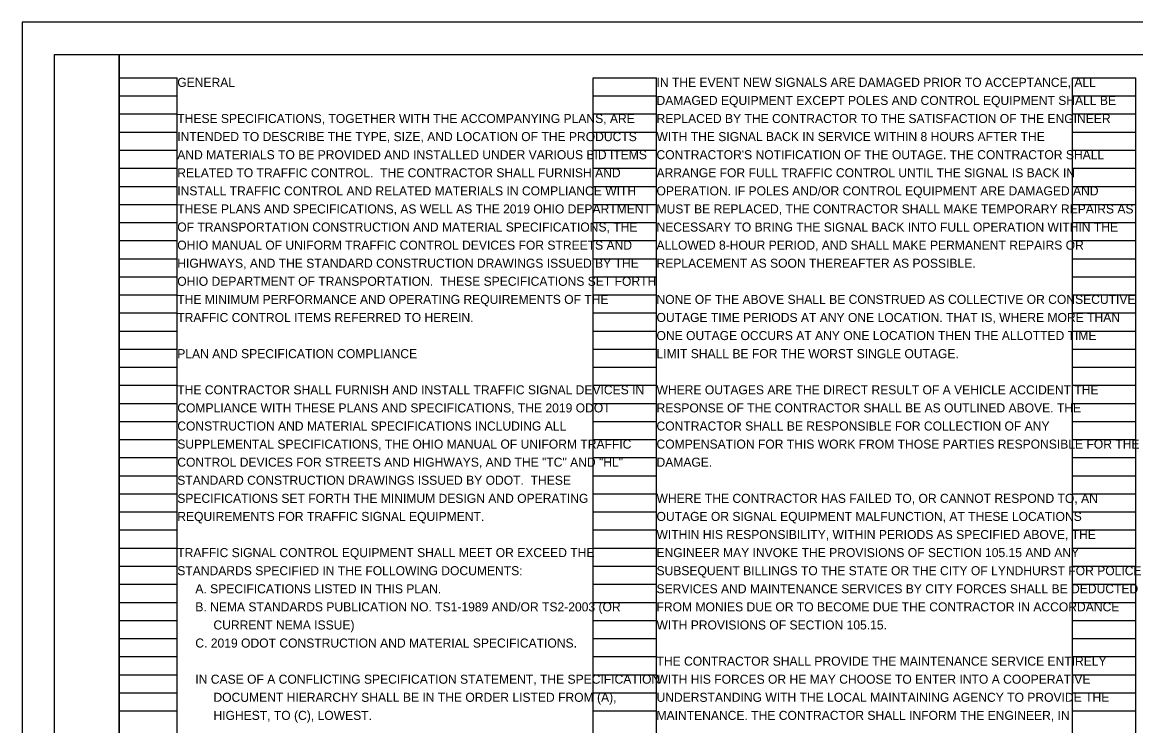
# Model space of a CAD drawing. Extents: x 0 to 34, y -30 to 22.
# Drawn here: x 0 to 17.24, y 11.11 to 22 of the extents above; entities that cross this region are included whole.
import ezdxf

# ---------------------------------------------------------------- set-up
doc = ezdxf.new("R2010")
doc.units = 0
for name, color, linetype in [('SH_Border', 7, 'Continuous'), ('SH_Cut_Line', 7, 'Continuous'), ('SH_Data', 7, 'Continuous'), ('SH_Text', 7, 'Continuous')]:
    doc.layers.add(name, color=color, linetype=linetype)

msp = doc.modelspace()

# ---------------------------------------------------------------- linework, layer by layer
at = {"layer": 'SH_Border'}
for points in [[(0.5, 21.5), (1.5, 21.5), (1.5, 0.5), (0.5, 0.5)], [(1.5, 21.5), (33.5, 21.5), (33.5, 0.5), (1.5, 0.5)]]:
    msp.add_lwpolyline(points, close=True, dxfattribs=at)
at = {"layer": 'SH_Cut_Line'}
msp.add_lwpolyline([(0, 0), (34, 0), (34, 22), (0, 22)], close=True, dxfattribs=at)
at = {"layer": 'SH_Data'}
for p, q in [((1.5, 0.98), (1.5, 21.14)), ((1.5, 21.14), (2.4, 21.14)), ((2.4, 0.98), (2.4, 21.14)), ((8.84, 0.98), (8.84, 21.14)), ((8.84, 21.14), (9.82, 21.14)), ((9.82, 0.98), (9.82, 21.14)), ((16.26, 0.98), (16.26, 21.14)), ((16.26, 21.14), (17.24, 21.14)), ((17.24, 0.98), (17.24, 21.14)), ((1.5, 20.86), (2.4, 20.86)), ((8.84, 20.86), (9.82, 20.86)), ((16.26, 20.86), (17.24, 20.86)), ((1.5, 20.58), (2.4, 20.58)), ((8.84, 20.58), (9.82, 20.58)), ((16.26, 20.58), (17.24, 20.58)), ((1.5, 20.3), (2.4, 20.3)), ((8.84, 20.3), (9.82, 20.3)), ((16.26, 20.3), (17.24, 20.3)), ((1.5, 20.02), (2.4, 20.02)), ((8.84, 20.02), (9.82, 20.02)), ((16.26, 20.02), (17.24, 20.02)), ((1.5, 19.74), (2.4, 19.74)), ((8.84, 19.74), (9.82, 19.74)), ((16.26, 19.74), (17.24, 19.74)), ((1.5, 19.46), (2.4, 19.46)), ((8.84, 19.46), (9.82, 19.46)), ((16.26, 19.46), (17.24, 19.46)), ((1.5, 19.18), (2.4, 19.18)), ((8.84, 19.18), (9.82, 19.18)), ((16.26, 19.18), (17.24, 19.18)), ((1.5, 18.9), (2.4, 18.9)), ((8.84, 18.9), (9.82, 18.9)), ((16.26, 18.9), (17.24, 18.9)), ((1.5, 18.62), (2.4, 18.62)), ((8.84, 18.62), (9.82, 18.62)), ((16.26, 18.62), (17.24, 18.62)), ((1.5, 18.34), (2.4, 18.34)), ((8.84, 18.34), (9.82, 18.34)), ((16.26, 18.34), (17.24, 18.34)), ((1.5, 18.06), (2.4, 18.06)), ((8.84, 18.06), (9.82, 18.06)), ((16.26, 18.06), (17.24, 18.06)), ((1.5, 17.78), (2.4, 17.78)), ((8.84, 17.78), (9.82, 17.78)), ((16.26, 17.78), (17.24, 17.78)), ((1.5, 17.5), (2.4, 17.5)), ((8.84, 17.5), (9.82, 17.5)), ((16.26, 17.5), (17.24, 17.5)), ((1.5, 17.22), (2.4, 17.22)), ((8.84, 17.22), (9.82, 17.22)), ((16.26, 17.22), (17.24, 17.22)), ((1.5, 16.94), (2.4, 16.94)), ((8.84, 16.94), (9.82, 16.94)), ((16.26, 16.94), (17.24, 16.94)), ((1.5, 16.66), (2.4, 16.66)), ((8.84, 16.66), (9.82, 16.66)), ((16.26, 16.66), (17.24, 16.66)), ((1.5, 16.38), (2.4, 16.38)), ((8.84, 16.38), (9.82, 16.38)), ((16.26, 16.38), (17.24, 16.38)), ((1.5, 16.1), (2.4, 16.1)), ((8.84, 16.1), (9.82, 16.1)), ((16.26, 16.1), (17.24, 16.1)), ((1.5, 15.82), (2.4, 15.82)), ((8.84, 15.82), (9.82, 15.82)), ((16.26, 15.82), (17.24, 15.82)), ((1.5, 15.54), (2.4, 15.54)), ((8.84, 15.54), (9.82, 15.54)), ((16.26, 15.54), (17.24, 15.54)), ((1.5, 15.26), (2.4, 15.26)), ((8.84, 15.26), (9.82, 15.26)), ((16.26, 15.26), (17.24, 15.26)), ((1.5, 14.98), (2.4, 14.98)), ((8.84, 14.98), (9.82, 14.98)), ((16.26, 14.98), (17.24, 14.98)), ((1.5, 14.7), (2.4, 14.7)), ((8.84, 14.7), (9.82, 14.7)), ((16.26, 14.7), (17.24, 14.7)), ((1.5, 14.42), (2.4, 14.42)), ((8.84, 14.42), (9.82, 14.42)), ((16.26, 14.42), (17.24, 14.42)), ((1.5, 14.14), (2.4, 14.14)), ((8.84, 14.14), (9.82, 14.14)), ((16.26, 14.14), (17.24, 14.14)), ((1.5, 13.86), (2.4, 13.86)), ((8.84, 13.86), (9.82, 13.86)), ((16.26, 13.86), (17.24, 13.86)), ((1.5, 13.58), (2.4, 13.58)), ((8.84, 13.58), (9.82, 13.58)), ((16.26, 13.58), (17.24, 13.58)), ((1.5, 13.3), (2.4, 13.3)), ((8.84, 13.3), (9.82, 13.3)), ((16.26, 13.3), (17.24, 13.3)), ((1.5, 13.02), (2.4, 13.02)), ((8.84, 13.02), (9.82, 13.02)), ((16.26, 13.02), (17.24, 13.02)), ((1.5, 12.74), (2.4, 12.74)), ((8.84, 12.74), (9.82, 12.74)), ((16.26, 12.74), (17.24, 12.74)), ((1.5, 12.46), (2.4, 12.46)), ((8.84, 12.46), (9.82, 12.46)), ((16.26, 12.46), (17.24, 12.46)), ((1.5, 12.18), (2.4, 12.18)), ((8.84, 12.18), (9.82, 12.18)), ((16.26, 12.18), (17.24, 12.18)), ((1.5, 11.9), (2.4, 11.9)), ((8.84, 11.9), (9.82, 11.9)), ((16.26, 11.9), (17.24, 11.9)), ((1.5, 11.62), (2.4, 11.62)), ((8.84, 11.62), (9.82, 11.62)), ((16.26, 11.62), (17.24, 11.62)), ((1.5, 11.34), (2.4, 11.34)), ((8.84, 11.34), (9.82, 11.34)), ((16.26, 11.34), (17.24, 11.34))]:
    msp.add_line(p, q, dxfattribs=at)

# ---------------------------------------------------------------- texts
at = {"layer": 'SH_Text'}
for s, p in [('GENERAL', (2.4, 21)), ('IN THE EVENT NEW SIGNALS ARE DAMAGED PRIOR TO ACCEPTANCE, ALL ', (9.82, 21)), ('DAMAGED EQUIPMENT EXCEPT POLES AND CONTROL EQUIPMENT SHALL BE ', (9.82, 20.72)), ('THESE SPECIFICATIONS, TOGETHER WITH THE ACCOMPANYING PLANS, ARE ', (2.4, 20.44)), ('REPLACED BY THE CONTRACTOR TO THE SATISFACTION OF THE ENGINEER ', (9.82, 20.44)), ('INTENDED TO DESCRIBE THE TYPE, SIZE, AND LOCATION OF THE PRODUCTS ', (2.4, 20.16)), ('WITH THE SIGNAL BACK IN SERVICE WITHIN 8 HOURS AFTER THE ', (9.82, 20.16)), ('AND MATERIALS TO BE PROVIDED AND INSTALLED UNDER VARIOUS BID ITEMS ', (2.4, 19.88)), ("CONTRACTOR'S NOTIFICATION OF THE OUTAGE. THE CONTRACTOR SHALL ", (9.82, 19.88)), ('RELATED TO TRAFFIC CONTROL.  THE CONTRACTOR SHALL FURNISH AND ', (2.4, 19.6)), ('ARRANGE FOR FULL TRAFFIC CONTROL UNTIL THE SIGNAL IS BACK IN ', (9.82, 19.6)), ('INSTALL TRAFFIC CONTROL AND RELATED MATERIALS IN COMPLIANCE WITH ', (2.4, 19.32)), ('OPERATION. IF POLES AND/OR CONTROL EQUIPMENT ARE DAMAGED AND ', (9.82, 19.32)), ('THESE PLANS AND SPECIFICATIONS, AS WELL AS THE 2019 OHIO DEPARTMENT ', (2.4, 19.04)), ('MUST BE REPLACED, THE CONTRACTOR SHALL MAKE TEMPORARY REPAIRS AS ', (9.82, 19.04)), ('OF TRANSPORTATION CONSTRUCTION AND MATERIAL SPECIFICATIONS, THE ', (2.4, 18.76)), ('NECESSARY TO BRING THE SIGNAL BACK INTO FULL OPERATION WITHIN THE ', (9.82, 18.76)), ('OHIO MANUAL OF UNIFORM TRAFFIC CONTROL DEVICES FOR STREETS AND ', (2.4, 18.48)), ('ALLOWED 8-HOUR PERIOD, AND SHALL MAKE PERMANENT REPAIRS OR ', (9.82, 18.48)), ('HIGHWAYS, AND THE STANDARD CONSTRUCTION DRAWINGS ISSUED BY THE ', (2.4, 18.2)), ('REPLACEMENT AS SOON THEREAFTER AS POSSIBLE.', (9.82, 18.2)), ('OHIO DEPARTMENT OF TRANSPORTATION.  THESE SPECIFICATIONS SET FORTH ', (2.4, 17.92)), ('THE MINIMUM PERFORMANCE AND OPERATING REQUIREMENTS OF THE ', (2.4, 17.64)), ('NONE OF THE ABOVE SHALL BE CONSTRUED AS COLLECTIVE OR CONSECUTIVE ', (9.82, 17.64)), ('TRAFFIC CONTROL ITEMS REFERRED TO HEREIN.', (2.4, 17.36)), ('OUTAGE TIME PERIODS AT ANY ONE LOCATION. THAT IS, WHERE MORE THAN ', (9.82, 17.36)), ('ONE OUTAGE OCCURS AT ANY ONE LOCATION THEN THE ALLOTTED TIME ', (9.82, 17.08)), ('PLAN AND SPECIFICATION COMPLIANCE', (2.4, 16.8)), ('LIMIT SHALL BE FOR THE WORST SINGLE OUTAGE.', (9.82, 16.8)), ('THE CONTRACTOR SHALL FURNISH AND INSTALL TRAFFIC SIGNAL DEVICES IN ', (2.4, 16.24)), ('WHERE OUTAGES ARE THE DIRECT RESULT OF A VEHICLE ACCIDENT THE ', (9.82, 16.24)), ('COMPLIANCE WITH THESE PLANS AND SPECIFICATIONS, THE 2019 ODOT ', (2.4, 15.96)), ('RESPONSE OF THE CONTRACTOR SHALL BE AS OUTLINED ABOVE. THE ', (9.82, 15.96)), ('CONSTRUCTION AND MATERIAL SPECIFICATIONS INCLUDING ALL ', (2.4, 15.68)), ('CONTRACTOR SHALL BE RESPONSIBLE FOR COLLECTION OF ANY ', (9.82, 15.68)), ('SUPPLEMENTAL SPECIFICATIONS, THE OHIO MANUAL OF UNIFORM TRAFFIC ', (2.4, 15.4)), ('COMPENSATION FOR THIS WORK FROM THOSE PARTIES RESPONSIBLE FOR THE ', (9.82, 15.4)), ('CONTROL DEVICES FOR STREETS AND HIGHWAYS, AND THE "TC" AND "HL" ', (2.4, 15.12)), ('DAMAGE.', (9.82, 15.12)), ('STANDARD CONSTRUCTION DRAWINGS ISSUED BY ODOT.  THESE ', (2.4, 14.84)), ('SPECIFICATIONS SET FORTH THE MINIMUM DESIGN AND OPERATING ', (2.4, 14.56)), ('WHERE THE CONTRACTOR HAS FAILED TO, OR CANNOT RESPOND TO, AN ', (9.82, 14.56)), ('REQUIREMENTS FOR TRAFFIC SIGNAL EQUIPMENT.  ', (2.4, 14.28)), ('OUTAGE OR SIGNAL EQUIPMENT MALFUNCTION, AT THESE LOCATIONS ', (9.82, 14.28)), ('WITHIN HIS RESPONSIBILITY, WITHIN PERIODS AS SPECIFIED ABOVE, THE ', (9.82, 14)), ('TRAFFIC SIGNAL CONTROL EQUIPMENT SHALL MEET OR EXCEED THE ', (2.4, 13.72)), ('ENGINEER MAY INVOKE THE PROVISIONS OF SECTION 105.15 AND ANY ', (9.82, 13.72)), ('STANDARDS SPECIFIED IN THE FOLLOWING DOCUMENTS:', (2.4, 13.44)), ('SUBSEQUENT BILLINGS TO THE STATE OR THE CITY OF LYNDHURST FOR POLICE ', (9.82, 13.44)), ('A. SPECIFICATIONS LISTED IN THIS PLAN. ', (2.68, 13.16)), ('SERVICES AND MAINTENANCE SERVICES BY CITY FORCES SHALL BE DEDUCTED ', (9.82, 13.16)), ('B. NEMA STANDARDS PUBLICATION NO. TS1-1989 AND/OR TS2-2003 (OR ', (2.68, 12.88)), ('FROM MONIES DUE OR TO BECOME DUE THE CONTRACTOR IN ACCORDANCE ', (9.82, 12.88)), ('CURRENT NEMA ISSUE) ', (2.96, 12.6)), ('WITH PROVISIONS OF SECTION 105.15.', (9.82, 12.6)), ('C. 2019 ODOT CONSTRUCTION AND MATERIAL SPECIFICATIONS.', (2.68, 12.32)), ('THE CONTRACTOR SHALL PROVIDE THE MAINTENANCE SERVICE ENTIRELY ', (9.82, 12.04)), ('IN CASE OF A CONFLICTING SPECIFICATION STATEMENT, THE SPECIFICATION ', (2.68, 11.76)), ('WITH HIS FORCES OR HE MAY CHOOSE TO ENTER INTO A COOPERATIVE ', (9.82, 11.76)), ('DOCUMENT HIERARCHY SHALL BE IN THE ORDER LISTED FROM (A), ', (2.96, 11.48)), ('UNDERSTANDING WITH THE LOCAL MAINTAINING AGENCY TO PROVIDE THE ', (9.82, 11.48)), ('HIGHEST, TO (C), LOWEST.', (2.96, 11.2)), ('MAINTENANCE. THE CONTRACTOR SHALL INFORM THE ENGINEER, IN ', (9.82, 11.2))]:
    msp.add_text(s, height=0.14, dxfattribs=at).set_placement(p)

doc.saveas('drawing.dxf')
